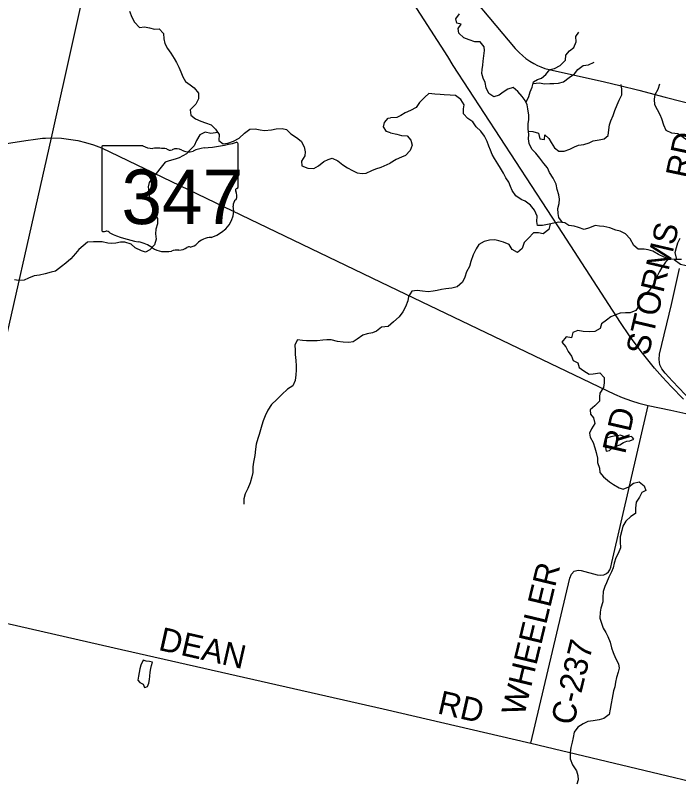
# Model space of a CAD drawing. Extents: x 0 to 34, y 0 to 22.
# Drawn here: x 3.488 to 4.289, y 15.74 to 16.669 of the extents above; entities that cross this region are included whole.
import ezdxf

# ---------------------------------------------------------------- set-up
doc = ezdxf.new("R2010")
doc.units = 0
for name, color, linetype in [('GM_X_County_Road', 7, 'Continuous'), ('GM_X_County_Road_Text', 7, 'Continuous'), ('GM_X_Minor_Lake', 7, 'Continuous'), ('GM_X_Minor_River', 7, 'Continuous'), ('GM_X_Rail_Line', 7, 'Continuous'), ('GM_X_State_Location', 7, 'Continuous'), ('GM_X_State_Route', 7, 'Continuous'), ('GM_X_State_Shield', 7, 'Continuous')]:
    doc.layers.add(name, color=color, linetype=linetype)

msp = doc.modelspace()

# ---------------------------------------------------------------- linework, layer by layer
at = {"layer": 'GM_X_County_Road'}
for points in [[(3.53142, 16.52054), (3.64166, 17.0172), (3.64227, 17.02074), (3.64796, 17.04616), (3.71506, 17.33606), (3.71682, 17.34442)], [(4.01317, 16.72243), (4.09165, 16.62872), (4.09652, 16.62371), (4.10101, 16.61968), (4.10468, 16.61657), (4.10922, 16.61342), (4.11428, 16.6104), (4.11859, 16.60822), (4.12271, 16.60646), (4.12754, 16.60456), (4.13278, 16.60308), (4.19959, 16.58838), (4.21828, 16.58388), (4.2409, 16.57809), (4.2728, 16.56979), (4.31555, 16.55875)], [(3.40134, 15.94724), (3.40046, 15.94912), (3.39947, 15.95296), (3.39996, 15.95759), (3.40608, 15.98272), (3.43542, 16.10391), (3.4589, 16.20132), (3.53142, 16.52054)], [(4.33028, 16.18009), (4.29715, 16.21009), (4.28157, 16.22618), (4.27292, 16.23604), (4.26894, 16.24123), (4.26652, 16.24625), (4.26566, 16.25248), (4.26617, 16.25888), (4.28071, 16.31927), (4.29033, 16.36254)], [(4.11047, 15.78873), (4.15782, 15.98816), (4.15958, 15.99278), (4.16297, 15.99658), (4.16759, 15.9978), (4.17139, 15.99734), (4.19056, 15.99225), (4.19483, 15.99166), (4.19869, 15.99207), (4.20214, 15.99365), (4.20459, 15.99599), (4.206, 15.99839), (4.20711, 16.00125), (4.2085, 16.00711), (4.25231, 16.19709)], [(3.14917, 15.78121), (3.40134, 15.94724), (3.40558, 15.94843), (3.4107, 15.94843), (3.48892, 15.93079), (3.60715, 15.90409), (3.93196, 15.83001), (4.11047, 15.78873), (4.46797, 15.70305), (4.4755, 15.70101), (4.48022, 15.69839), (4.48401, 15.69487)]]:
    msp.add_lwpolyline(points, dxfattribs=at)
at = {"layer": 'GM_X_Minor_Lake'}
for points in [[(4.20213, 16.15752), (4.20174, 16.1543), (4.20095, 16.14633), (4.20169, 16.14178), (4.20567, 16.14233), (4.20909, 16.14573), (4.21365, 16.1478), (4.21801, 16.14949), (4.22238, 16.15213), (4.22655, 16.15401), (4.23034, 16.15419), (4.23508, 16.15607), (4.23331, 16.15821)], [(4.23331, 16.15821), (4.23225, 16.15949), (4.22827, 16.15856), (4.22373, 16.15895), (4.219, 16.16106), (4.21521, 16.16031), (4.21123, 16.15976), (4.20706, 16.15902), (4.20213, 16.15752)], [(3.64198, 15.88912), (3.63929, 15.88288), (3.63813, 15.87852), (3.63735, 15.87398), (3.63638, 15.86962), (3.63559, 15.8647), (3.63823, 15.86184), (3.64201, 15.85993), (3.6435, 15.85594), (3.64509, 15.85652)], [(3.64509, 15.85652), (3.64711, 15.85725), (3.64902, 15.86103), (3.64981, 15.86576), (3.65021, 15.86974), (3.65061, 15.87448), (3.6514, 15.87883), (3.65218, 15.88262), (3.65333, 15.88641), (3.64955, 15.88737), (3.64576, 15.88796), (3.64198, 15.88912)]]:
    msp.add_lwpolyline(points, dxfattribs=at)
at = {"layer": 'GM_X_Minor_River'}
for points in [[(3.62554, 16.674), (3.62834, 16.66659), (3.63171, 16.66051), (3.63774, 16.65422), (3.64381, 16.65495), (3.64986, 16.65359), (3.65573, 16.65205), (3.66123, 16.65259), (3.6665, 16.64668), (3.66722, 16.64043), (3.66814, 16.63474), (3.67133, 16.62884), (3.67565, 16.62314), (3.67959, 16.61648), (3.68222, 16.61173), (3.68503, 16.60603), (3.68746, 16.60052), (3.69008, 16.59425), (3.69327, 16.58893), (3.69893, 16.58473), (3.70384, 16.58111), (3.70873, 16.57483), (3.70888, 16.56763)], [(4.14872, 16.41825), (4.14454, 16.42434), (4.14343, 16.42909), (4.14327, 16.43516), (4.14463, 16.44141), (4.14523, 16.44653), (4.1445, 16.45165), (4.14246, 16.45811), (4.14117, 16.46476), (4.13761, 16.47198), (4.1331, 16.47883), (4.13048, 16.48454), (4.12616, 16.48968), (4.12146, 16.49615), (4.11638, 16.50225), (4.11186, 16.50702), (4.10868, 16.51367), (4.10776, 16.51937), (4.10798, 16.52486), (4.10745, 16.53132), (4.10749, 16.53757), (4.10809, 16.54269), (4.10793, 16.54819), (4.10683, 16.55559), (4.10591, 16.56072), (4.10386, 16.56585), (4.09991, 16.57061), (4.09502, 16.57652), (4.08918, 16.58167), (4.08291, 16.57962), (4.07721, 16.57567), (4.07208, 16.57228), (4.06562, 16.57004), (4.05978, 16.57444), (4.05659, 16.5809), (4.0555, 16.58754), (4.05288, 16.59287), (4.05139, 16.59838), (4.05161, 16.60331), (4.0524, 16.60842), (4.05299, 16.61316), (4.05359, 16.6196), (4.05439, 16.62605), (4.05404, 16.63079), (4.04915, 16.6367), (4.04271, 16.63692), (4.03609, 16.63904), (4.02948, 16.64174), (4.02364, 16.64708), (4.02291, 16.65296), (4.02635, 16.65825), (4.02124, 16.65942), (4.01995, 16.66473), (4.02415, 16.67059)], [(4.1047, 16.56375), (4.10806, 16.57057), (4.10979, 16.57644), (4.11229, 16.58192), (4.11384, 16.58817), (4.11878, 16.59118), (4.12352, 16.59286), (4.12866, 16.59738), (4.13343, 16.60323), (4.13931, 16.60453), (4.14596, 16.60829), (4.15244, 16.61451), (4.15285, 16.62076), (4.15724, 16.62586), (4.16237, 16.63), (4.16525, 16.63682), (4.16472, 16.64308), (4.16854, 16.64837)], [(4.11343, 16.58652), (4.12046, 16.587), (4.12765, 16.58601), (4.13352, 16.58617), (4.13845, 16.58652), (4.14395, 16.58687), (4.1502, 16.58816), (4.15667, 16.59362), (4.16333, 16.59795), (4.16715, 16.60343), (4.17361, 16.60813), (4.18006, 16.60905), (4.1869, 16.61223)], [(4.10766, 16.5288), (4.11312, 16.52844), (4.11973, 16.52613), (4.1214, 16.51948), (4.12708, 16.5185), (4.1273, 16.52438), (4.1322, 16.51999), (4.13501, 16.51485), (4.13895, 16.50839), (4.14442, 16.50437), (4.15067, 16.50434), (4.1577, 16.50676), (4.16339, 16.50958), (4.16833, 16.51164), (4.17478, 16.51255), (4.18085, 16.5146), (4.18597, 16.51685), (4.19299, 16.51814), (4.19906, 16.51943), (4.20382, 16.52339), (4.20499, 16.53021), (4.20578, 16.53627), (4.20733, 16.54119), (4.2102, 16.54744), (4.21213, 16.55368), (4.21501, 16.56069), (4.21732, 16.56617), (4.22058, 16.57279), (4.22043, 16.57962), (4.21989, 16.58493)], [(4.30108, 16.51656), (4.28805, 16.52533), (4.28085, 16.52612), (4.27423, 16.52937), (4.27123, 16.53582), (4.26899, 16.54361), (4.26673, 16.54855), (4.26372, 16.55444), (4.26034, 16.56052), (4.25999, 16.56754), (4.26076, 16.57285), (4.26439, 16.57966), (4.2665, 16.58591)], [(3.70888, 16.56763), (3.70581, 16.5612), (3.69895, 16.55441), (3.69986, 16.54796), (3.70533, 16.54376), (3.71175, 16.5407), (3.71724, 16.53859), (3.72424, 16.53647), (3.72951, 16.53094), (3.73383, 16.52467), (3.73341, 16.51747), (3.73889, 16.51346), (3.74438, 16.51419), (3.75141, 16.51661), (3.75825, 16.52018), (3.76435, 16.5264), (3.77082, 16.53111), (3.77745, 16.53164), (3.78332, 16.53028), (3.78881, 16.52969), (3.79734, 16.53021), (3.80265, 16.5317), (3.81004, 16.53204), (3.81515, 16.53069), (3.82062, 16.52554), (3.82741, 16.52115), (3.83307, 16.51657), (3.83645, 16.50992), (3.83774, 16.50366), (3.83733, 16.49892), (3.83332, 16.4925), (3.83366, 16.48662), (3.84085, 16.48393), (3.84824, 16.4837), (3.85413, 16.48671), (3.86041, 16.49198), (3.86554, 16.49442), (3.87047, 16.49591), (3.87747, 16.49284), (3.88331, 16.48807), (3.88897, 16.48425), (3.89483, 16.481), (3.9005, 16.4785), (3.90656, 16.47753), (3.91149, 16.47788), (3.91833, 16.48125), (3.92326, 16.48312), (3.92972, 16.48498), (3.94035, 16.49005)], [(4.28365, 16.3737), (4.27684, 16.3745), (4.27155, 16.37623), (4.26493, 16.3795), (4.25814, 16.38351), (4.25247, 16.38525), (4.24754, 16.38585), (4.24016, 16.38589), (4.23488, 16.39047), (4.23076, 16.39865), (4.22511, 16.40437), (4.21831, 16.40763), (4.21339, 16.40898), (4.20602, 16.41187), (4.19883, 16.41324), (4.19334, 16.41384), (4.18823, 16.41443), (4.1814, 16.41162), (4.17514, 16.40995), (4.16833, 16.41208), (4.16285, 16.41362), (4.1566, 16.41461), (4.15151, 16.41786), (4.14451, 16.41884), (4.13825, 16.41736), (4.13066, 16.4157), (4.12459, 16.41459), (4.11853, 16.41444), (4.1178, 16.41937), (4.11803, 16.42582), (4.11485, 16.43323), (4.10996, 16.43914), (4.10374, 16.4441), (4.09882, 16.44603), (4.09222, 16.45061), (4.0879, 16.45689), (4.08584, 16.46165), (4.08379, 16.46697), (4.08041, 16.4723), (4.0776, 16.47781), (4.07404, 16.48409), (4.07047, 16.48923), (4.06653, 16.4957), (4.0639, 16.50064), (4.06166, 16.50559), (4.05998, 16.51053), (4.05774, 16.51604), (4.05437, 16.5225), (4.05024, 16.5286), (4.04458, 16.53394), (4.04064, 16.54003), (4.0346, 16.54385), (4.02933, 16.54957), (4.02918, 16.55583), (4.03015, 16.56057), (4.02583, 16.56685), (4.01942, 16.57181), (4.01298, 16.57223), (4.00579, 16.57265), (4.00086, 16.57286), (3.99462, 16.57347), (3.98742, 16.57408), (3.98228, 16.56974), (3.97581, 16.56352), (3.97199, 16.55747), (3.96515, 16.55353), (3.9585, 16.55072), (3.95337, 16.54752), (3.94862, 16.54509), (3.94096, 16.54467)], [(3.94076, 16.52662), (3.93621, 16.52835), (3.93265, 16.53386), (3.93381, 16.53898), (3.93801, 16.54426), (3.94096, 16.54467)], [(3.73227, 16.52694), (3.7238, 16.52604), (3.7168, 16.52741), (3.71052, 16.52422), (3.7067, 16.51742), (3.70382, 16.51099), (3.69906, 16.50646), (3.69448, 16.50137), (3.68574, 16.4963), (3.6808, 16.495), (3.67359, 16.49295), (3.66865, 16.49108), (3.66369, 16.48523), (3.65759, 16.47749), (3.65358, 16.47259), (3.64938, 16.46655), (3.64821, 16.46143), (3.64893, 16.45499), (3.64984, 16.44797), (3.65151, 16.44133), (3.65337, 16.43544), (3.65523, 16.42937), (3.65936, 16.4231), (3.65952, 16.41646), (3.6574, 16.41022), (3.6568, 16.40435), (3.65771, 16.3979), (3.65577, 16.39128), (3.65024, 16.38524), (3.64492, 16.38243), (3.64, 16.38378), (3.63245, 16.3878), (3.62736, 16.39199), (3.61979, 16.3945), (3.61486, 16.39433), (3.60899, 16.39341), (3.60425, 16.39287), (3.59951, 16.39308), (3.59232, 16.39483), (3.58701, 16.39485), (3.58209, 16.39469), (3.57488, 16.39435), (3.56937, 16.39021), (3.56441, 16.38569), (3.56041, 16.38078), (3.5545, 16.37437), (3.54879, 16.36909), (3.54327, 16.36514), (3.53604, 16.3593), (3.53091, 16.358), (3.52351, 16.35634), (3.51687, 16.35466), (3.51042, 16.35356), (3.5034, 16.35094), (3.49808, 16.34851), (3.49144, 16.34797), (3.48652, 16.34876)], [(3.94076, 16.52662), (3.94851, 16.52517), (3.95437, 16.52362), (3.96118, 16.52302), (3.9657, 16.51768), (3.96718, 16.5118), (3.96468, 16.50517), (3.95915, 16.49913), (3.95441, 16.49726), (3.94776, 16.49446), (3.94035, 16.49005)], [(4.13389, 16.41641), (4.13214, 16.40981), (4.12548, 16.40473), (4.11962, 16.4059), (4.11375, 16.40555), (4.10765, 16.39914), (4.10251, 16.39423), (4.10019, 16.38666), (4.09448, 16.38195), (4.08806, 16.38559), (4.08431, 16.39149), (4.0777, 16.39456), (4.07202, 16.39592), (4.06691, 16.39727), (4.06047, 16.39674), (4.05421, 16.39526), (4.04775, 16.3915), (4.04431, 16.3864), (4.04086, 16.37902), (4.03817, 16.37107), (4.03624, 16.36501), (4.03279, 16.35859), (4.03086, 16.35215), (4.02779, 16.34591), (4.02151, 16.34063), (4.01488, 16.33896), (4.00786, 16.33805), (4.00274, 16.33713), (3.99743, 16.33602), (3.99251, 16.33529), (3.98644, 16.33457), (3.97963, 16.33517), (3.97319, 16.33597), (3.96656, 16.33525), (3.96273, 16.32882), (3.96175, 16.32351), (3.95925, 16.31613), (3.956, 16.31008), (3.95123, 16.30404), (3.94456, 16.2982), (3.93813, 16.29239)], [(4.28679, 16.37369), (4.28502, 16.38177), (4.28637, 16.38821), (4.2881, 16.39352), (4.29115, 16.39919)], [(4.27721, 16.37446), (4.27323, 16.37024), (4.26885, 16.364), (4.26599, 16.35908), (4.26293, 16.35245), (4.26045, 16.34677), (4.25759, 16.34166), (4.25283, 16.33466), (4.24637, 16.33014), (4.24123, 16.32409), (4.24101, 16.31764), (4.23758, 16.31177), (4.23056, 16.30914), (4.22488, 16.30916), (4.21863, 16.30862), (4.21388, 16.30712), (4.20724, 16.3043), (4.20192, 16.30033), (4.19603, 16.29561), (4.1945, 16.29012), (4.18785, 16.28654), (4.18122, 16.28619), (4.17383, 16.2864), (4.16721, 16.28776), (4.16114, 16.28531), (4.1596, 16.27887), (4.15316, 16.27984), (4.14783, 16.27341), (4.15293, 16.26809), (4.15574, 16.26219), (4.1597, 16.25668), (4.16176, 16.25117), (4.16744, 16.2485), (4.16912, 16.2428), (4.1746, 16.23899), (4.18121, 16.23498), (4.18595, 16.23534), (4.19372, 16.23664), (4.19919, 16.23093), (4.19917, 16.22448), (4.19839, 16.21879), (4.19381, 16.21198), (4.19342, 16.20724), (4.19359, 16.20231), (4.18788, 16.19645), (4.18237, 16.19173), (4.18254, 16.18661), (4.18631, 16.18185), (4.1878, 16.17521), (4.18399, 16.16859), (4.1815, 16.16347), (4.18205, 16.15873), (4.186, 16.15208), (4.18806, 16.14581), (4.18956, 16.13993), (4.19105, 16.13328), (4.19122, 16.12816), (4.19346, 16.12132), (4.19382, 16.11601), (4.19854, 16.1105), (4.20552, 16.10459), (4.21062, 16.10134), (4.21724, 16.09734), (4.22216, 16.0958), (4.22899, 16.09862), (4.23469, 16.10296), (4.24132, 16.10464), (4.24756, 16.09988), (4.24943, 16.09418), (4.2445, 16.09174), (4.24201, 16.08606), (4.23763, 16.08), (4.23703, 16.0728), (4.2372, 16.06616), (4.23131, 16.06277), (4.22542, 16.05691), (4.2218, 16.05085), (4.22045, 16.04574), (4.21853, 16.03816), (4.21831, 16.0319), (4.21904, 16.02469), (4.21599, 16.01787), (4.21331, 16.01257), (4.21121, 16.00613), (4.21005, 16.00082), (4.20814, 15.9959), (4.20489, 15.98946), (4.20183, 15.98265), (4.20011, 15.97791), (4.19782, 15.97185), (4.19741, 15.96464), (4.19739, 15.95971), (4.19528, 15.95194), (4.1945, 15.9472), (4.19409, 15.93981), (4.19596, 15.93354), (4.19803, 15.92766), (4.20123, 15.92252), (4.20367, 15.91777), (4.2063, 15.91055), (4.20798, 15.90391)], [(4.28365, 16.3737), (4.29157, 16.36778), (4.29838, 16.36642), (4.30557, 16.36467), (4.31257, 16.36349), (4.31938, 16.36156), (4.32562, 16.35963), (4.3328, 16.35693), (4.33942, 16.35424), (4.34603, 16.35079), (4.35207, 16.34735), (4.35925, 16.34389), (4.36567, 16.34082), (4.37246, 16.33642), (4.37869, 16.3326), (4.38529, 16.32706), (4.39171, 16.32399), (4.39815, 16.3232), (4.40496, 16.32259), (4.41214, 16.31971), (4.41894, 16.31645), (4.4246, 16.31167), (4.42892, 16.30558), (4.43438, 16.30062)], [(4.29274, 16.37365), (4.28365, 16.3737)], [(3.93813, 16.29239), (3.92995, 16.29187), (3.92405, 16.28697), (3.9193, 16.28491), (3.91266, 16.28343), (3.90754, 16.28194), (3.90069, 16.27724), (3.89594, 16.27385), (3.89044, 16.27331), (3.88362, 16.27373), (3.87699, 16.27433), (3.86942, 16.27646), (3.86393, 16.27629), (3.85919, 16.27613), (3.85217, 16.27522), (3.84668, 16.27506), (3.83948, 16.27528), (3.83456, 16.27569), (3.8285, 16.27629), (3.82543, 16.27024), (3.82558, 16.26342), (3.82574, 16.25849), (3.82646, 16.25128), (3.82699, 16.24484), (3.82696, 16.23972), (3.82674, 16.23385), (3.82576, 16.22722), (3.82307, 16.2206), (3.8166, 16.21684), (3.80975, 16.21044), (3.80346, 16.20421), (3.79717, 16.19818), (3.79277, 16.19119), (3.78933, 16.18458), (3.78721, 16.17852), (3.78566, 16.17323), (3.78393, 16.16755), (3.78238, 16.16187), (3.78046, 16.15695), (3.77871, 16.15014), (3.77773, 16.14408), (3.77712, 16.1365), (3.77556, 16.12855), (3.77477, 16.12268), (3.77473, 16.11586), (3.77338, 16.11075), (3.77125, 16.10337), (3.76856, 16.09656), (3.76549, 16.09013), (3.76375, 16.08389), (3.76372, 16.07763)], [(4.20798, 15.90391), (4.20985, 15.89821), (4.21304, 15.89156), (4.21643, 15.88472), (4.21717, 15.87941), (4.2162, 15.87429), (4.2139, 15.86804), (4.21275, 15.86235), (4.21197, 15.85666), (4.21062, 15.85174), (4.2087, 15.84283), (4.20753, 15.83657), (4.20656, 15.82975), (4.20502, 15.82312), (4.19875, 15.81859), (4.19325, 15.81671), (4.18586, 15.81579), (4.17942, 15.81468), (4.17372, 15.81204), (4.16746, 15.80808), (4.16289, 15.80203), (4.16154, 15.79558), (4.16057, 15.7899), (4.15884, 15.78326), (4.15787, 15.7772), (4.15823, 15.7698), (4.16104, 15.76258), (4.16556, 15.75535), (4.16724, 15.74966), (4.16779, 15.74434), (4.16626, 15.73904)]]:
    msp.add_lwpolyline(points, dxfattribs=at)
at = {"layer": 'GM_X_Rail_Line'}
msp.add_lwpolyline([(4.29501, 16.20448), (4.28004, 16.21976), (4.26974, 16.23107), (4.26011, 16.24196), (4.25334, 16.25006), (4.24546, 16.26011), (4.23771, 16.27037), (4.22996, 16.28111), (4.21886, 16.29751), (4.14915, 16.40485), (4.01655, 16.60829), (4.0102, 16.6191), (3.96919, 16.68265), (3.70466, 17.09019), (3.65524, 17.16647), (3.5976, 17.25517), (3.54023, 17.34366), (3.44378, 17.49231), (3.4061, 17.55045), (3.31865, 17.68521), (3.20063, 17.86743), (3.08515, 18.04522)], dxfattribs=at)
at = {"layer": 'GM_X_State_Route'}
msp.add_lwpolyline([(3.32458, 16.48745), (3.32507, 16.48756), (3.36687, 16.49593), (3.40089, 16.50195), (3.46371, 16.51168), (3.5004, 16.51739), (3.51185, 16.51914), (3.5205, 16.52006), (3.524, 16.52033), (3.53142, 16.52054), (3.54338, 16.52009), (3.55458, 16.51876), (3.56291, 16.51732), (3.57257, 16.51495), (3.58203, 16.51207), (3.5917, 16.50837), (3.93927, 16.34142), (4.2118, 16.21045), (4.22104, 16.20644), (4.23216, 16.20243), (4.2412, 16.19986), (4.25231, 16.19709), (4.27968, 16.19123), (4.33028, 16.18009)], dxfattribs=at)
at = {"layer": 'GM_X_State_Shield'}
for p, q in [((3.59193, 16.50934), (3.59193, 16.40928)), ((3.64182, 16.51106), (3.59356, 16.51106)), ((3.75673, 16.46119), (3.75673, 16.51354)), ((3.75671, 16.46121), (3.75673, 16.46119))]:
    msp.add_line(p, q, dxfattribs=at)
for centre, major_axis, start_param, end_param in [((3.59382, 16.50955), (0.00191, 0), 1.712693, 3.28349), ((3.65331, 16.52267), (0.01852, 0), 4.042523, 4.731795), ((3.69802, 16.64747), (0.17476, 0), 4.814394, 5.042369), ((3.7549, 16.51375), (0.00183, 0), 6.141152, 7.989035), ((3.65945, 16.45488), (0.06648, 0), 1.404758, 1.657858), ((3.67454, 16.51007), (0.00534, 0), 3.836095, 5.185415), ((3.68238, 16.4985), (0.01111, 0), 0.950623, 2.079405), ((3.69672, 16.51436), (0.01336, 0), 4.081561, 5.145723), ((3.72032, 16.4805), (0.03516, 0), 1.699011, 2.107814), ((3.7563, 16.45735), (0.00284, 0), 1.883978, 3.671073), ((3.73824, 16.45073), (0.01704, 0), 5.934695, 6.695948), ((3.75477, 16.46099), (0.00196, 0), 5.05454, 6.418171), ((3.7633, 16.43929), (0.0124, 0), 2.387724, 3.262537), ((3.70781, 16.43263), (0.04371, 0), 5.101752, 6.440018), ((3.59384, 16.40906), (0.00193, 0), 3.00124, 4.508301), ((3.59413, 16.41929), (0.0147, 0), 4.665946, 4.897461), ((3.59714, 16.4035), (0.0053, 0), 0.519207, 1.627899), ((3.66405, 16.4934), (0.1262, 0), 4.195997, 4.488961), ((3.72625, 16.38118), (0.02394, 0), 1.647645, 2.488434), ((3.62643, 16.36432), (0.03949, 0), 0.823519, 1.323587), ((3.69752, 16.38582), (0.00376, 0), 1.147584, 2.315152), ((3.69591, 16.39958), (0.01412, 0), 4.937069, 5.64225), ((3.66913, 16.40301), (0.02506, 0), 4.026481, 4.996735), ((3.68361, 16.36841), (0.02059, 0), 1.495662, 1.94098), ((3.68544, 16.39551), (0.01335, 0), 4.691044, 5.507374)]:
    msp.add_ellipse(centre, major_axis=major_axis, ratio=0.8, start_param=start_param, end_param=end_param, dxfattribs=at)

# ---------------------------------------------------------------- texts
at = {"layer": 'GM_X_County_Road_Text'}
for s, rotation, p in [('RD', 78.11018, (4.30103, 16.47042)), ('STORMS', 76.82682, (4.25275, 16.25611)), ('RD', 77.04182, (4.22441, 16.13729)), ('WHEELER', 76.48771, (4.10235, 15.82032)), ('DEAN', 347.22899, (3.65944, 15.90152)), ('C-237', 76.36491, (4.16202, 15.80899)), ('RD', 347.15207, (3.99653, 15.82485))]:
    msp.add_text(s, height=0.028409, rotation=rotation, dxfattribs=at).set_placement(p)
at = {"layer": 'GM_X_State_Location'}
msp.add_text('347', height=0.0000947, rotation=0.00001, dxfattribs=at).set_placement((3.63905, 16.44576))
for s, p in [('s', (3.67248, 16.45265)), ('r', (3.67247, 16.45265))]:
    msp.add_text(s, height=0.0000947, dxfattribs=at).set_placement(p)
at = {"layer": 'GM_X_State_Shield'}
msp.add_text('347', height=0.065918, dxfattribs=at).set_placement((3.61586, 16.41633))

doc.saveas('drawing.dxf')
